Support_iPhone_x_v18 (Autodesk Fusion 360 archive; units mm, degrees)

design "Support iPhone x" references "iPhone X"
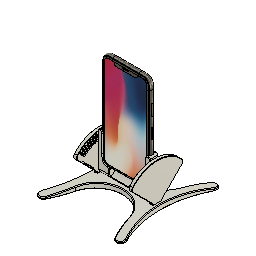
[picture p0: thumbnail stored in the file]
parameter "Toleranceprint" = -0.05
component_insert "Component Insert"
sketch "Sketch1" plane through (0, 0, 0) normal (1, 0, 0) x axis (0, 1, 0)
  curve K1 (7.6763, -69.2022) -> (7.5594, -69.219)
  curve K2 (3.929, -68.0059) -> (6.6572, -69.2439)
  curve K3 (7.7739, -69.1847) -> (10.1998, -67.7023)
  line L1 (10.1998, -53.4756) -> (10.1998, -67.7023)
  line L2 (3.8498, -53.4756) -> (3.8498, -67.8028)
  line L3 (3.8498, 58.5344) -> (3.8498, -53.4756)
  line L4 (3.8498, 72.8616) -> (3.8498, 58.5344)
  line L5 (10.1998, 58.5344) -> (10.1998, -53.4756)
  curve K4 (3.929, 73.0647) -> (10.1998, 72.7611)
  line L6 (10.1998, 72.7639) -> (10.1998, 58.5344)
  curve K5 (7.6763, -69.2022) -> (7.5594, -69.219)
  line L7 (6.2966, -69.203) -> (6.2876, -69.2016)
  curve K6 (7.6853, -69.2009) -> (7.6045, -69.213)
  line L8 (7.5376, -69.2217) -> (7.5262, -69.2231)
  curve K7 (7.6678, -69.2035) -> (7.5377, -69.2217)
  curve K8 (7.9032, -69.1604) -> (7.8661, -69.1678)
  line L9 (13.3666, -23.4558) -> (0.633, -23.4558)
  line L10 (13.3666, -81.2716) -> (13.3666, -23.4558)
  line L11 (0.633, -81.2716) -> (13.3666, -81.2716)
  line L12 (0.633, -23.4558) -> (0.633, -81.2716)
  line L13 (10.8498, -65.0156) -> (3.1498, -65.0156)
  arc A1 centre (4.1498, 72.8615) radius 0.3 clockwise from (3.8498, 72.8615) to (3.929, 73.0647)
  arc A2 centre (4.1498, -67.8028) radius 0.3 clockwise from (3.929, -68.0059) to (3.8498, -67.8028)
  arc A3 centre (0.633, -66.9061) radius 12.7335 clockwise from (13.3666, -66.9061) to (0.633, -79.6396)
  point P36 (13.3666, -66.9061)
  point P35 (0.633, -79.6396)
  point P37 (0.633, -66.9061)
  point P38 (3.1498, -65.0156)
  point P40 (3.1498, -65.0156)
  point P39 (10.8498, -65.0156)
  point P41 (10.8498, -65.0156)
  point P42 (6.9998, -65.0156)
  point P43 (6.9998, -81.2716)
  horizontal L9
  vertical L10
  horizontal L11
  vertical L12
  tangent L10 A3
  coincident L10 P36
  coincident L12 P35
  coincident L12 P37
  perpendicular L1 L13
  vertical P38 P40
  vertical P39 P41
  coincident P39 P41
  midpoint L13 P42
  midpoint L11 P43
  vertical P42 P43
extrude "Extrude1" new body sketch "Sketch1" profile of L9 L10 L11 L12 A3 distance 38.1
sketch "Sketch2" plane through (0, 0.633, 0) normal (0, -1, 0) x axis (1, 0, 0)
  line L1 (17, 68.6344) -> (17, 69.1044)
  line L2 (-13.78, 65.4144) -> (13.78, 65.4144)
  line L3 (-17, 69.1044) -> (-17, 68.6344)
  line L4 (-19.26, 70.0744) -> (-17.4345, 70.0744)
  curve K1 (-19.26, 70.0744) -> (-31.23, 58.5344)
  line L5 (-31.23, -53.4756) -> (-31.23, 58.5344)
  curve K2 (-31.23, -53.4756) -> (-19.26, -65.0156)
  line L6 (19.26, -65.0156) -> (-19.26, -65.0156)
  curve K3 (19.26, -65.0156) -> (31.23, -53.4756)
  line L7 (31.23, 58.5344) -> (31.23, -53.4756)
  curve K4 (31.23, 58.5344) -> (19.26, 70.0744)
  line L8 (17.4345, 70.0744) -> (19.26, 70.0744)
  arc A1 centre (18.3, 69.1044) radius 1.3 clockwise from (17, 69.1044) to (17.4345, 70.0744)
  arc A2 centre (13.78, 68.6344) radius 3.22 clockwise from (17, 68.6344) to (13.78, 65.4144)
  arc A3 centre (-13.78, 68.6344) radius 3.22 clockwise from (-13.78, 65.4144) to (-17, 68.6344)
  arc A4 centre (-18.3, 69.1044) radius 1.3 clockwise from (-17.4345, 70.0744) to (-17, 69.1044)
sketch "Sketch3" plane through (0, 0, -23.4558) normal (0, 0, 1) x axis (-1, 0, 0)
  curve K1 (34.2203, -3.929) -> (33.9167, -10.1998)
  line L1 (31.23, -10.8498) -> (19.26, -10.8498)
  curve K2 (31.5609, -3.1588) -> (19.26, -3.1588)
  line L2 (27.8577, -2.6588) -> (27.8577, -11.3498)
  curve K3 (31.23, -10.8498) -> (33.9167, -10.1998)
  line L3 (31.5159, -7.0043) -> (27.8577, -7.0043)
  curve K4 (33.7773, -10.2934) -> (34.056, -10.1062)
  curve K5 (30.8065, -10.8498) -> (31.6535, -10.8498)
  curve K6 (34.2203, -3.929) -> (31.5609, -3.1588)
  line L4 (31.23, -11.3498) -> (19.26, -11.3498)
  curve K7 (31.23, -11.3498) -> (34.1954, -10.6149)
  curve K8 (34.5588, -3.5611) -> (34.1954, -10.6149)
  curve K9 (34.5588, -3.5611) -> (31.5727, -2.6589)
  curve K10 (31.5727, -2.6589) -> (19.26, -2.6588)
  point P2 (33.9167, -10.1998)
  point P8 (33.9167, -10.1998)
  point P5 (31.23, -10.8498)
  point P9 (31.23, -10.8498)
  point P7 (31.5609, -3.1588)
  point P16 (31.5609, -3.1588)
  point P3 (34.2203, -3.929)
  point P17 (34.2203, -3.929)
  point P24 (27.8577, -11.3498)
  point P10 (27.8577, -7.0043)
  point P25 (27.8577, -2.6588)
  perpendicular L1 L2
  coincident P2 P8
  coincident P5 P9
  perpendicular L2 L3
  midpoint P8 K4
  midpoint P9 K5
  coincident P7 P16
  coincident P3 P17
  coincident L4 P24
  coincident L2 P10
  coincident K10 P25
  dimension "d10" = -0.5
sweep "Sweep1" sketch "Sketch3" TwistAngle 0 TaperAngle 0
delete_face "DeleteFace3"
delete_face "DeleteFace4"
delete_face "DeleteFace5"
sketch "Sketch4" plane through (0, 0, -23.4558) normal (0, 0, 1) x axis (-1, 0, 0)
  line L1 (-31.23, -11.3498) -> (-27.8577, -11.3498)
  curve K1 (-34.1954, -10.6149) -> (-31.23, -11.3498)
  curve K2 (-34.5588, -3.5611) -> (-34.1954, -10.6149)
  curve K3 (-31.5727, -2.6589) -> (-34.5588, -3.5611)
  curve K4 (-27.8577, -2.6588) -> (-31.5727, -2.6589)
  line L2 (-27.8577, -11.3498) -> (-27.8577, -2.6588)
  line L3 (27.8577, -2.6588) -> (27.8577, -11.3498)
  curve K5 (31.5727, -2.6589) -> (27.8577, -2.6588)
  curve K6 (34.5588, -3.5611) -> (31.5727, -2.6589)
  curve K7 (34.1954, -10.6149) -> (34.5588, -3.5611)
  curve K8 (31.23, -11.3498) -> (34.1954, -10.6149)
  line L4 (27.8577, -11.3498) -> (31.23, -11.3498)
  line L5 (-27.8577, -11.3498) -> (27.8577, -11.3498)
  line L6 (27.8577, -2.6588) -> (-27.8577, -2.6588)
  point P8 (27.8577, -11.3498)
  point P14 (27.8577, -11.3498)
  point P2 (-27.8577, -11.3498)
  point P15 (-27.8577, -11.3498)
  point P7 (-27.8577, -2.6588)
  point P16 (-27.8577, -2.6588)
  point P9 (27.8577, -2.6588)
  point P17 (27.8577, -2.6588)
  coincident P8 P14
  coincident P2 P15
  coincident P7 P16
  coincident P9 P17
extrude "Extrude2" cut sketch "Sketch4" profile of L2 L3 L5 L6 against normal blind 33.02
delete_face "DeleteFace6"
extrude "Extrude3" cut sketch "Sketch2" against normal blind 3.81
fillet "Fillet1" radius 6.3668 (= "0.50132 in / 2")
sketch "Sketch5" plane through (0, 0, 0) normal (1, 0, 0) x axis (0, 1, 0)
  curve K1 (2.6589, -65.3583) -> (3.5611, -68.3444)
  curve K2 (2.6588, -65.0156) -> (2.6589, -65.3583)
  line L1 (0.633, -65.0156) -> (2.6588, -65.0156)
  line L2 (0.633, -74.9048) -> (0.633, -65.0156)
  line L3 (13.3666, -23.4558) -> (13.3666, -74.9048)
  line L4 (11.3498, -23.4558) -> (13.3666, -23.4558)
  line L5 (11.3498, -65.0156) -> (11.3498, -23.4558)
  curve K3 (10.6149, -67.9811) -> (11.3498, -65.0156)
  curve K4 (3.5611, -68.3444) -> (10.6149, -67.9811)
  line L6 (0.1528, -59.2569) -> (0.633, -65.0156)
  line L7 (11.3498, -59.2569) -> (0.1528, -59.2569)
  arc A1 centre (6.9998, -74.9048) radius 6.3668 clockwise from (6.9998, -81.2716) to (0.633, -74.9048)
  arc A2 centre (6.9998, -74.9048) radius 6.3668 clockwise from (13.3666, -74.9048) to (6.9998, -81.2716)
  arc A3 centre (-4.7745, -65.0156) radius 16.1243 clockwise from (11.3498, -65.0156) to (2.4978, -79.4068)
  point P16 (2.4978, -79.4068)
  point P13 (11.3498, -65.0156)
  point P15 (11.3498, -65.0156)
  point P5 (0.633, -65.0156)
  point P18 (0.633, -65.0156)
  point P20 (11.3498, -59.2569)
  midpoint A1 P16
  coincident P13 P15
  tangent L5 A3
  coincident P5 P18
  coincident L5 P20
  perpendicular L5 L7
extrude "Extrude4" cut sketch "Sketch5" profile of K1 K2 L1 L2 A1 L5 K3 K4 A3 L6 L7 distance 21.59
fillet "Fillet2" radius 3.81
delete_face "DeleteFace7"
fillet "Fillet3" radius 21.463
fillet "Fillet4" radius 3.81
fillet "Fillet5" radius 2.54
chamfer "Chamfer1" distance 1
fillet "Fillet6" radius 0.254
sketch "Sketch6" plane through (38.1, 0, 0) normal (1, 0, 0) x axis (0, 1, 0)
  line L1 (12.3666, -25.9958) -> (12.3666, -74.9048)
  line L2 (1.633, -25.9958) -> (12.3666, -25.9958)
  line L3 (1.633, -74.9048) -> (1.633, -25.9958)
  line L4 (6.0245, -38.2923) -> (6.0245, -30.742)
  line L5 (7.9751, -30.742) -> (7.9751, -38.2923)
  line L6 (6.9998, -38.2923) -> (6.9998, -30.742)
  arc A1 centre (6.9998, -74.9048) radius 5.3668 clockwise from (6.9998, -80.2716) to (1.633, -74.9048)
  arc A2 centre (6.9998, -74.9048) radius 5.3668 clockwise from (12.3666, -74.9048) to (6.9998, -80.2716)
  circle C1 centre (6.9998, -74.9048) radius 1.905
  arc A3 centre (6.9998, -38.2923) radius 0.9753 clockwise from (7.9751, -38.2923) to (6.0245, -38.2923)
  arc A4 centre (6.9998, -30.742) radius 0.9753 clockwise from (6.0245, -30.742) to (7.9751, -30.742)
  point P16 (6.9998, -34.5171)
  point P17 (6.9998, -25.9958)
  point P14 (6.9998, -30.742)
  point P15 (6.9998, -38.2923)
  concentric A2 C1
  tangent L4 A3
  tangent A3 L5
  parallel L4 L5
  tangent L5 A4
  tangent L4 A4
  vertical L6
  midpoint L6 P16
  midpoint L2 P17
  vertical P14 P17
  dimension "d24" diameter C1 = 3.81
  dimension "d30" distance L2 P14 = 4.7461
  dimension "d31" distance L4 L5 = 1.9506
  dimension "d32" distance P14 P15 = 7.5503
extrude "Extrude5" add sketch "Sketch6" profile of C1 L4 A3 L5 A4 along normal blind 1.27
chamfer "Chamfer2" distance 0.508
mirror "Mirror1" mirrorStitchTolerance 0.1001
work_plane "WorkPlane1" AlongDistance -80.518
split "Split1"
remove_body "RemoveBody1"
sketch "Sketch2" plane through (0, 0, 0) normal (1, 0, 0) x axis (0, 1, 0)
  line L1 (46.0682, -47.6688) -> (14.3573, -79.3797)
  line L2 (13.3666, -87.6048) -> (13.3666, -81.7716)
  line L3 (-1.367, -87.6048) -> (13.3666, -87.6048)
  line L4 (13.4037, -81.2716) -> (-0.2814, -81.2716)
  line L5 (7.9751, -38.2923) -> (7.9751, -30.742)
  line L6 (6.0245, -30.742) -> (6.0245, -38.2923)
  line L7 (22.4346, -68.474) -> (35.1625, -55.7461)
  line L8 (7.4671, -38.2923) -> (7.4671, -30.742)
  line L9 (6.5325, -30.742) -> (6.5325, -38.2923)
  line L10 (-18.5587, -48.6854) -> (-23.8976, -43.3466)
  line L11 (-24.5585, -44.0074) -> (-19.2196, -49.3463)
  line L12 (-15.8657, -46.3065) -> (-20.6556, -40.47)
  line L13 (-21.378, -41.0629) -> (-16.5882, -46.8994)
  line L14 (-12.9525, -44.203) -> (-17.1472, -37.9251)
  line L15 (-17.9243, -38.4444) -> (-13.7296, -44.7222)
  line L16 (-9.8471, -42.3952) -> (-13.4063, -35.7364)
  line L17 (-14.2305, -36.177) -> (-10.6713, -42.8357)
  line L18 (-6.5795, -40.9004) -> (-9.4689, -33.9249)
  line L19 (-10.3323, -34.2825) -> (-7.4429, -41.2581)
  line L20 (-3.1811, -39.7332) -> (-5.3728, -32.508)
  line L21 (-6.2672, -32.7793) -> (-4.0754, -40.0045)
  line L22 (0.3154, -38.9046) -> (-1.1576, -31.4994)
  line L23 (-2.0743, -31.6817) -> (-0.6013, -39.087)
  line L24 (30.2128, -63.5243) -> (28.7985, -62.11)
  line L25 (3.8762, -38.4228) -> (3.1361, -30.9088)
  line L26 (2.206, -31.0004) -> (2.9461, -38.5144)
  line L27 (11.0535, -38.5144) -> (11.7936, -31.0004)
  line L28 (10.8635, -30.9088) -> (10.1234, -38.4228)
  line L29 (14.6009, -39.087) -> (16.0739, -31.6817)
  line L30 (15.1572, -31.4994) -> (13.6842, -38.9046)
  line L31 (18.075, -40.0045) -> (20.2668, -32.7793)
  line L32 (19.3724, -32.508) -> (17.1807, -39.7332)
  line L33 (6.9998, -51.1337) -> (6.9998, -74.9048)
  line L34 (-0.8577, -78.8797) -> (-32.0686, -47.6688)
  line L35 (-8.435, -68.474) -> (-21.1629, -55.7461)
  line L36 (0.133, -81.2716) -> (0.133, -87.6048)
  line L37 (21.4425, -41.2581) -> (24.3319, -34.2825)
  line L38 (23.4685, -33.9249) -> (20.5791, -40.9004)
  line L39 (24.671, -42.8357) -> (28.2301, -36.177)
  line L40 (27.4059, -35.7364) -> (23.8467, -42.3952)
  line L41 (27.7292, -44.7222) -> (31.9239, -38.4444)
  line L42 (31.1468, -37.9252) -> (26.9521, -44.203)
  line L43 (30.5878, -46.8994) -> (35.3776, -41.0629)
  line L44 (34.6552, -40.47) -> (29.8653, -46.3065)
  line L45 (33.2192, -49.3463) -> (38.5581, -44.0074)
  line L46 (37.8972, -43.3466) -> (32.5584, -48.6854)
  circle C1 centre (6.9998, -74.9048) radius 1.905
  arc A1 centre (6.9998, -74.9048) radius 47.625 clockwise from (-32.0686, -47.6688) to (46.0682, -47.6688)
  arc A2 centre (6.9998, -74.9048) radius 6.3668 clockwise from (13.3666, -74.9048) to (10.0045, -80.518)
  arc A3 centre (16.7492, -81.7716) radius 3.3826 clockwise from (13.3666, -81.7716) to (14.3573, -79.3797)
  arc A4 centre (6.9998, -74.9048) radius 6.3668 clockwise from (10.0045, -80.518) to (0.633, -74.9048)
  arc A5 centre (6.9998, -30.742) radius 0.9753 clockwise from (6.0245, -30.742) to (7.9751, -30.742)
  arc A6 centre (6.9998, -38.2923) radius 0.9753 clockwise from (7.9751, -38.2923) to (6.0245, -38.2923)
  circle C2 centre (6.9998, -74.9048) radius 2.205
  arc A7 centre (35.8696, -56.4532) radius 1 clockwise from (35.1625, -55.7461) to (36.5767, -57.1603)
  arc A8 centre (23.1417, -69.1811) radius 1 clockwise from (23.8488, -69.8882) to (22.4346, -68.474)
  arc A9 centre (6.9998, -38.2923) radius 0.4673 clockwise from (7.4671, -38.2923) to (6.5325, -38.2923)
  arc A10 centre (6.9998, -30.742) radius 0.4673 clockwise from (6.5325, -30.742) to (7.4671, -30.742)
  arc A11 centre (-18.8892, -49.0159) radius 0.4673 clockwise from (-18.5587, -48.6854) to (-19.2196, -49.3463)
  arc A12 centre (-24.228, -43.677) radius 0.4673 clockwise from (-24.5585, -44.0074) to (-23.8976, -43.3466)
  arc A13 centre (-16.2269, -46.603) radius 0.4673 clockwise from (-15.8657, -46.3065) to (-16.5882, -46.8994)
  arc A14 centre (-21.0168, -40.7665) radius 0.4673 clockwise from (-21.378, -41.0629) to (-20.6556, -40.47)
  arc A15 centre (-13.341, -44.4626) radius 0.4673 clockwise from (-12.9525, -44.203) to (-13.7296, -44.7222)
  arc A16 centre (-17.5358, -38.1848) radius 0.4673 clockwise from (-17.9243, -38.4444) to (-17.1472, -37.9251)
  arc A17 centre (-10.2592, -42.6154) radius 0.4673 clockwise from (-9.8471, -42.3952) to (-10.6713, -42.8357)
  arc A18 centre (-13.8184, -35.9567) radius 0.4673 clockwise from (-14.2305, -36.177) to (-13.4063, -35.7364)
  arc A19 centre (-7.0112, -41.0793) radius 0.4673 clockwise from (-6.5795, -40.9004) to (-7.4429, -41.2581)
  arc A20 centre (-9.9006, -34.1037) radius 0.4673 clockwise from (-10.3323, -34.2825) to (-9.4689, -33.9249)
  arc A21 centre (-3.6283, -39.8688) radius 0.4673 clockwise from (-3.1811, -39.7332) to (-4.0754, -40.0045)
  arc A22 centre (-5.82, -32.6436) radius 0.4673 clockwise from (-6.2672, -32.7793) to (-5.3728, -32.508)
  arc A23 centre (-0.1429, -38.9958) radius 0.4673 clockwise from (0.3154, -38.9046) to (-0.6013, -39.087)
  arc A24 centre (-1.6159, -31.5906) radius 0.4673 clockwise from (-2.0743, -31.6817) to (-1.1576, -31.4994)
  arc A25 centre (3.4111, -38.4686) radius 0.4673 clockwise from (3.8762, -38.4228) to (2.9461, -38.5144)
  arc A26 centre (2.6711, -30.9546) radius 0.4673 clockwise from (2.206, -31.0004) to (3.1361, -30.9088)
  arc A27 centre (10.5885, -38.4686) radius 0.4673 clockwise from (11.0535, -38.5144) to (10.1234, -38.4228)
  arc A28 centre (11.3285, -30.9546) radius 0.4673 clockwise from (10.8635, -30.9088) to (11.7936, -31.0004)
  arc A29 centre (14.1426, -38.9958) radius 0.4673 clockwise from (14.6009, -39.087) to (13.6842, -38.9046)
  arc A30 centre (15.6155, -31.5906) radius 0.4673 clockwise from (15.1572, -31.4994) to (16.0739, -31.6817)
  arc A31 centre (17.6279, -39.8688) radius 0.4673 clockwise from (18.075, -40.0045) to (17.1807, -39.7332)
  arc A32 centre (19.8196, -32.6436) radius 0.4673 clockwise from (19.3724, -32.508) to (20.2668, -32.7793)
  arc A33 centre (-21.87, -56.4532) radius 1 clockwise from (-22.5771, -57.1603) to (-21.1629, -55.7461)
  arc A34 centre (-9.1421, -69.1811) radius 1 clockwise from (-8.435, -68.474) to (-9.8492, -69.8882)
  arc A35 centre (-3.2496, -81.2716) radius 3.3826 clockwise from (-0.8577, -78.8797) to (0.133, -81.2716)
  arc A36 centre (21.0108, -41.0793) radius 0.4673 clockwise from (21.4425, -41.2581) to (20.5791, -40.9004)
  arc A37 centre (23.9002, -34.1037) radius 0.4673 clockwise from (23.4685, -33.9249) to (24.3319, -34.2825)
  arc A38 centre (24.2588, -42.6155) radius 0.4673 clockwise from (24.671, -42.8357) to (23.8467, -42.3952)
  arc A39 centre (27.818, -35.9567) radius 0.4673 clockwise from (27.4059, -35.7364) to (28.2301, -36.177)
  arc A40 centre (27.3406, -44.4626) radius 0.4673 clockwise from (27.7292, -44.7222) to (26.9521, -44.203)
  arc A41 centre (31.5354, -38.1848) radius 0.4673 clockwise from (31.1468, -37.9252) to (31.9239, -38.4444)
  arc A42 centre (30.2266, -46.603) radius 0.4673 clockwise from (30.5878, -46.8994) to (29.8653, -46.3065)
  arc A43 centre (35.0164, -40.7665) radius 0.4673 clockwise from (34.6552, -40.47) to (35.3776, -41.0629)
  arc A44 centre (32.8888, -49.0159) radius 0.4673 clockwise from (33.2192, -49.3463) to (32.5584, -48.6854)
  arc A45 centre (38.2277, -43.677) radius 0.4673 clockwise from (37.8972, -43.3466) to (38.5581, -44.0074)
  point P2 (6.9998, -74.9048)
  point P5 (6.9998, -74.9048)
  point P8 (10.0045, -80.518)
  point P16 (10.0045, -80.518)
  point P14 (6.9998, -74.9048)
  point P18 (13.4037, -81.2716)
  point P28 (36.5767, -57.1603)
  point P30 (23.8488, -69.8882)
  point P9 (13.3666, -74.9048)
  point P80 (28.7985, -62.11)
  point P81 (30.2128, -63.5243)
  point P10 (6.9998, -74.9048)
  point P106 (6.9998, -74.9048)
  point P111 (-22.5771, -57.1603)
  point P113 (-9.8492, -69.8882)
  point P115 (0.133, -87.6048)
  point P116 (0.133, -81.2716)
  point P31 (23.1417, -69.1811)
  point P114 (-9.1421, -69.1811)
  point P11 (13.3666, -81.7716)
  point P4 (-1.367, -87.6048)
  point P13 (13.3666, -87.6048)
  point P26 (35.1625, -55.7461)
  point P27 (22.4346, -68.474)
  coincident P2 P5
  tangent A3 L2
  coincident P8 P16
  coincident P5 P14
  tangent A4 L4
  coincident A3 P18
  perpendicular L2 L4
  concentric A1 C2
  parallel L1 L7
  tangent A2 L7
  coincident L1 P28
  tangent L7 A7
  coincident L1 P30
  tangent L7 A8
  tangent L1 A3
  coincident P9 L2
  tangent L1 A7
  tangent L1 A8
  parallel L5 L8
  concentric A6 A9
  parallel L6 L9
  concentric A5 A10
  tangent L8 A10
  tangent L8 A9
  tangent A9 L9
  tangent L9 A10
  horizontal L3
  midpoint L7 P80
  midpoint L1 P81
  perpendicular L1 L24
  coincident P10 P106
  vertical L33
  parallel L34 L35
  coincident L34 P111
  tangent L35 A33
  coincident L34 P113
  tangent L35 A34
  tangent L34 A34
  tangent L34 A33
  tangent A4 L35
  coincident L3 P115
  coincident L4 P116
  perpendicular L4 L36
  tangent L36 A35
  tangent L34 A35
  equal A3 A35
  equal L7 L35
  horizontal P31 P114
  dimension "d40" distance P5 L3 = 12.7
  dimension "d41" distance P11 L4 = 0.5
  dimension "d42" radius A1 = 47.625
  dimension "d77" distance C1 C2 = 0.3
  dimension "d78" distance L1 L7 = 2
  dimension "d85" distance L8 L9 = 0.9346
  dimension "d89" distance P4 P13 = 14.7335
  dimension "d90" distance P11 P13 = 5.8332
  dimension "d91" angle L1 L3 = 45
  dimension "d92" distance P26 P27 = 18
  dimension "d93" angle L3 L34 = 45
  dimension "d94" distance L34 L35 = 2 (= "d78")
  dimension "d45" C-Pattern1-Angle = -90
extrude "Extrude1" sketch "Sketch2" profile of L1 A1 A3 L2 L3 A10 L8 A9 L9 C2 L7 A7 A8 L10 A11 L11 A12 L12 A13 L13 A14 L14 A15 L15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 blind 5 from offset 0.2
extrude "Extrude2" sketch "Sketch2" profile of A10 L8 A9 L9 L10 A11 L11 A12 L12 A13 L13 A14 L14 A15 L15 A16 L16 A17 L17 A18 L18 A19 L19 A20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 blind 1
extrude "Extrude3" sketch "Sketch2" profile of L1 L7 A7 A8 L24 L34 L35 A33 A34 blind -3
chamfer "Chamfer1" distance 1
fillet "Fillet1" radius 5.08
chamfer "Chamfer2" distance 0.5
mirror_component "MirrorComponent1"
derived_instance "DerivedInstance1"
sketch "Sketch1" plane through (0, 0, -87.6048) normal (0, 0, -1) x axis (1, 0, 0)
  line L1 (38.3, -12.8666) -> (38.3, -0.633)
  line L2 (38.3, -12.8666) -> (38.8, -13.3666)
  line L3 (42.8, -13.3666) -> (38.8, -13.3666)
  line L4 (42.8, -13.3666) -> (43.3, -12.8666)
  line L5 (43.3, -0.633) -> (43.3, -12.8666)
  line L6 (0, -45.8151) -> (0, 22.4025)
  line L7 (38.35, -6.7498) -> (43.25, -6.7498)
  line L8 (38.8207, -0.183) -> (38.35, -0.6537)
  line L9 (38.8207, -0.183) -> (42.7793, -0.183)
  line L10 (43.25, -0.6537) -> (42.7793, -0.183)
  line L11 (38.35, -12.8459) -> (38.35, -0.6537)
  line L12 (38.35, -12.8459) -> (38.8207, -13.3166)
  line L13 (42.7793, -13.3166) -> (38.8207, -13.3166)
  line L14 (42.7793, -13.3166) -> (43.25, -12.8459)
  line L15 (43.25, -0.6537) -> (43.25, -12.8459)
  line L16 (43.3, -0.633) -> (42.8, -0.133)
  line L17 (38.8, -0.133) -> (42.8, -0.133)
  line L18 (38.8, -0.133) -> (38.3, -0.633)
  line L19 (0, -6.7498) -> (40.8, -6.7498)
  arc A1 centre (190.8, -6.7498) radius 143.6933 clockwise from (62.5221, -71.4997) to (62.5221, 58.0001)
  arc A2 centre (56.892, 60.842) radius 6.3067 clockwise from (51.2619, 63.6838) to (62.5221, 58.0001)
  arc A3 centre (190.8, -6.7498) radius 156.3067 clockwise from (51.2619, -77.1834) to (51.2619, 63.6838)
  arc A4 centre (56.892, -74.3416) radius 6.3067 clockwise from (62.5221, -71.4997) to (51.2619, -77.1834)
  arc A5 centre (190.8, -6.7498) radius 150 clockwise from (56.892, -74.3416) to (56.892, 60.842)
  arc A6 centre (0, -55.1402) radius 40.5341 clockwise from (0, -14.6061) to (39.2901, -45.1755)
  arc A7 centre (0, 41.6406) radius 40.5341 clockwise from (39.2901, 31.6759) to (0, 1.1065)
  point P19 (40.8, -6.7498)
  point P21 (0, -14.6061)
  point P20 (39.2901, -45.1755)
  point P24 (0, 1.1065)
  point P23 (39.2901, 31.6759)
  point P22 (0, -55.1402)
  point P25 (0, 41.6406)
  point P18 (38.35, -6.7498)
  point P17 (43.25, -6.7498)
  point P16 (190.8, -6.7498)
  point P1 (0, 0)
  point P38 (40.8, -6.7498)
  point P39 (0, -6.7498)
  vertical L6
  tangent A1 A2
  tangent A2 A3
  tangent A3 A4
  tangent A1 A4
  midpoint L7 P19
  coincident A5 P19
  coincident L6 P21
  coincident A3 P20
  coincident L6 P24
  coincident A3 P23
  tangent A3 A6
  coincident L6 P22
  tangent A3 A7
  coincident L6 P25
  parallel L8 L18
  parallel L9 L17
  parallel L10 L16
  parallel L1 L11
  parallel L2 L12
  parallel L3 L13
  parallel L4 L14
  parallel L5 L15
  midpoint P18 L11
  midpoint P17 L15
  midpoint A5 P19
  horizontal P16 P19
  coincident P1 L6
  coincident P19 P38
  coincident L6 P39
  perpendicular L6 L19
  symmetric A6 A7 L19
  dimension "d54" radius A2 = 6.3067
  dimension "d55" radius A5 = 150
  dimension "d95" distance L5 L15 = -0.05 (= "Toleranceprint")
  dimension "d96" distance L10 L16 = -0.05 (= "d95")
  dimension "d97" distance L9 L17 = -0.05 (= "d95")
  dimension "d98" distance L8 L18 = -0.05 (= "d95")
  dimension "d99" distance L1 L11 = -0.05 (= "d95")
  dimension "d100" distance L4 L14 = -0.05 (= "d95")
  dimension "d101" distance L3 L13 = -0.05 (= "d95")
  dimension "d102" distance L2 L12 = -0.05 (= "d95")
extrude "Extrude1" new body sketch "Sketch1" profile of L6 A1 A2 A3 A4 A6 A7 L8 L11 L9 L10 L15 L14 L13 L12 against normal blind 10
extrude "Extrude2" add sketch "Sketch1" profile of L6 A1 A2 A3 A4 A6 A7 L8 L11 L9 L10 L15 L14 L13 L12 along normal blind 2
mirror "Mirror1" mirrorStitchTolerance 0.1
combine "Combine1"
sketch "Sketch2" plane through (0, 0, 0) normal (1, 0, 0) x axis (0, 1, 0)
  line L1 (12.8459, -77.6048) -> (0.6537, -77.6048)
  line L2 (6.7498, -50.7978) -> (6.7498, -77.6048)
  line L3 (141.4997, -98.3671) -> (-128.0001, -98.3671)
  arc A1 centre (6.7498, -631.6048) radius 550 clockwise from (-128.0001, -98.3671) to (141.4997, -98.3671)
  point P7 (6.7498, -77.6048)
  point P4 (6.7498, -631.6048)
  point P8 (6.7498, -50.7978)
  midpoint L1 P7
  perpendicular L1 L2
  vertical P4 P8
  horizontal L3
  dimension "d104" radius A1 = 550
  dimension "d105" distance A1 L1 = 4
extrude "Extrude3" new body distance 70
step "ReplaceFace"
remove_body "RemoveBody1"
chamfer "Chamfer1" distance 1
as_built_joint "As-built1"
as_built_joint "As-built2"
as_built_joint "As-built3" OffsetX 0 OffsetY 0 OffsetZ 0 AngleZ 0 AngleMinimum -45 AngleMaximum 45
as_built_joint "As-built4" OffsetX 0 OffsetY 0 OffsetZ 0 AngleZ 0 DistanceMinimum 0
extrude "Extrude4" sketch "Sketch2" profile of C2 blind 2
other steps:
derived_base_feature "Derived Base Feature"
create_component "CreateComponent1"
create_component "CreateComponent2"
create_component "CreateComponent3"
create_component "CreateComponent4"

design "iPhone X"
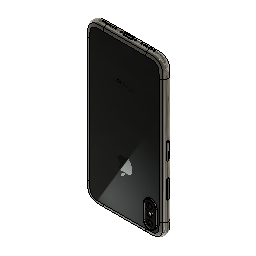
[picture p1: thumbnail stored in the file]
